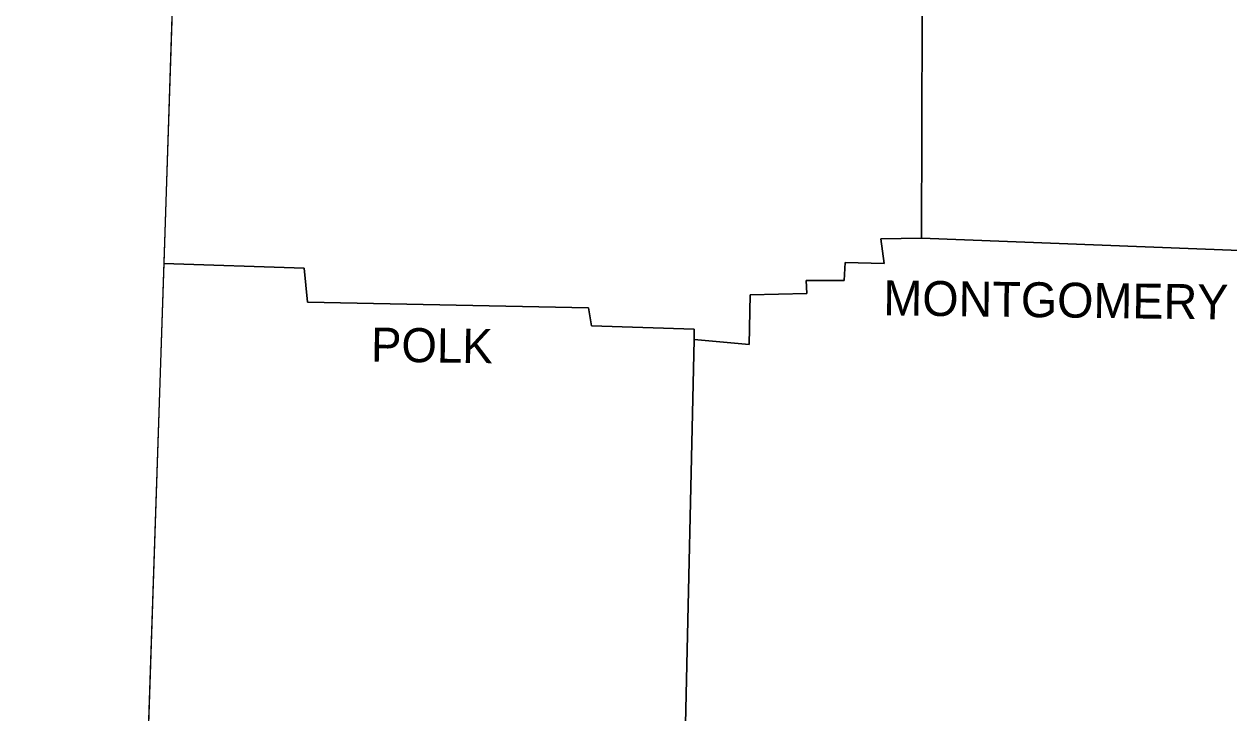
# Model space of a CAD drawing. Extents: x -28335 to 1228743, y -22428 to 152440.
# Drawn here: x 24268 to 27629, y 10013 to 11936 of the extents above; entities that cross this region are included whole.
import ezdxf

# ---------------------------------------------------------------- set-up
doc = ezdxf.new("R2010")
doc.units = 0
doc.layers.add('R_Draft', color=7, linetype='Continuous')
doc.layers.add('R_No Plot', color=7, linetype='Continuous')

msp = doc.modelspace()

# ---------------------------------------------------------------- linework, layer by layer
at = {"layer": 'R_Draft'}
for points in [[(24268.3, 17422.7), (24737.2, 13657.8), (24533.3, 7512.2)], [(26774.6, 12266.1), (26771.5, 11338.2), (26658.2, 11336), (26667.3, 11268), (26558.5, 11270.3), (26556.3, 11220.4), (26449.8, 11220.4), (26452.1, 11184.2), (26293.5, 11179.7), (26291.2, 11041.5), (26137.2, 11055.1), (26112.3, 9940.6), (25240.1, 9942.8), (25219.7, 9684.6), (25251.4, 9662), (25249.2, 9372), (24596, 9400.7)], [(27659.5, 11304.3), (26771.5, 11338.2)], [(24657.9, 11268), (25049.8, 11254.4), (25058.9, 11159.3), (25842.7, 11143.4), (25851.7, 11093.6), (26137.2, 11084.5), (26137.2, 11055.1)]]:
    msp.add_lwpolyline(points, dxfattribs=at)
at = {"layer": 'R_No Plot'}
for p, q in [((26774.6, 12266.1), (26771.5, 11338.2)), ((24681.7, 11985.7), (24657.9, 11268)), ((26771.5, 11338.2), (27659.5, 11304.3)), ((27659.5, 11304.3), (26771.5, 11338.2)), ((24657.9, 11268), (24596, 9400.7)), ((26558.5, 11270.3), (26556.3, 11220.4)), ((26667.3, 11268), (26558.5, 11270.3)), ((26293.5, 11179.7), (26291.2, 11041.5)), ((26452.1, 11184.2), (26293.5, 11179.7))]:
    msp.add_line(p, q, dxfattribs=at)
for points in [[(26137.2, 11055.1), (26291.2, 11041.5), (26293.5, 11179.7), (26452.1, 11184.2), (26449.8, 11220.4), (26556.3, 11220.4), (26558.5, 11270.3), (26667.3, 11268), (26658.2, 11336), (26771.5, 11338.2), (26774.6, 12266.1)], [(26771.5, 11338.2), (26658.2, 11336), (26667.3, 11268)], [(26137.2, 11055.1), (26137.2, 11084.5), (25851.7, 11093.6), (25842.7, 11143.4), (25058.9, 11159.3), (25049.8, 11254.4), (24657.9, 11268)], [(24657.9, 11268), (25049.8, 11254.4), (25058.9, 11159.3), (25842.7, 11143.4), (25851.7, 11093.6)], [(26556.3, 11220.4), (26449.8, 11220.4), (26452.1, 11184.2)], [(25851.7, 11093.6), (26137.2, 11084.5), (26137.2, 11055.1)], [(24596, 9400.7), (25249.2, 9372), (25251.4, 9662), (25219.7, 9684.6), (25240.1, 9942.8), (26112.3, 9940.6), (26137.2, 11055.1)], [(26291.2, 11041.5), (26137.2, 11055.1), (26112.3, 9940.6)]]:
    msp.add_lwpolyline(points, dxfattribs=at)

# ---------------------------------------------------------------- texts
at = {"layer": 'R_Draft'}
for s, height, rotation, p in [('MONTGOMERY', 97.42, 359.2944, (26665, 11123)), ('POLK', 95.13, 359.2152, (25235.6, 10993.9))]:
    msp.add_text(s, height=height, rotation=rotation, dxfattribs=at).set_placement(p)

doc.saveas('drawing.dxf')
